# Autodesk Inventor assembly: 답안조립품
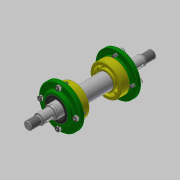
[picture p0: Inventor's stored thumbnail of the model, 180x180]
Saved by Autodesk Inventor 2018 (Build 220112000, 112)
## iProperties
Created: 2023-10
Part Number: 답안조립품
Material: 일반
Document SubType Name: Assembly
Designer: home
Author: home
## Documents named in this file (7)
- C:\Users\home\Desktop\731006V1004\답안조립품.iam
- C:\Users\home\Desktop\731006V1004\본체.ipt
- C:\Users\home\Desktop\731006V1004\커버.ipt
- C:\Users\home\Desktop\731006V1004\오일실 20x35x8.ipt
- C:\Users\home\Desktop\731006V1004\베어링 6204.ipt
- C:\Users\home\Desktop\731006V1004\축.ipt
- C:\Users\home\Desktop\731006V1004\볼트 M4x0.7.ipt
